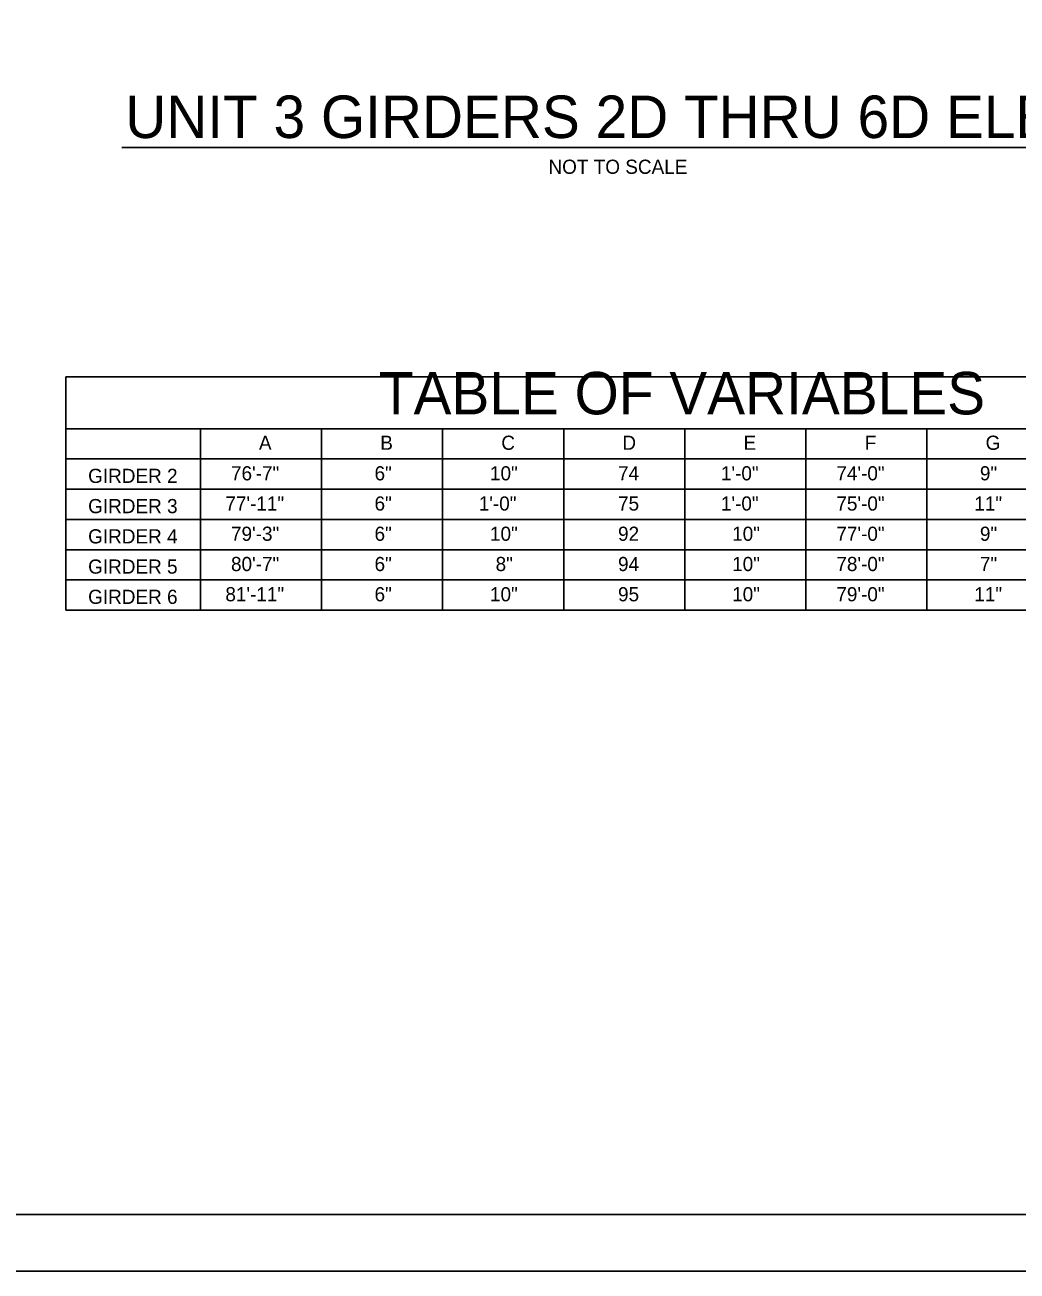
# Model space of a CAD drawing. Extents: x -305 to -161, y -187 to -99.
# Drawn here: x -251.38 to -216.35, y -187.49 to -143.49 of the extents above; entities that cross this region are included whole.
import ezdxf

# ---------------------------------------------------------------- set-up
doc = ezdxf.new("R2010")
doc.units = 0
for name, color, linetype in [('BR_AUTO DIMENSION', 7, 'Continuous'), ('BR_BORDER LINES', 7, 'Continuous'), ('BR_TEXT', 7, 'Continuous'), ('Level 31', 7, 'Continuous')]:
    doc.layers.add(name, color=color, linetype=linetype)

msp = doc.modelspace()

# ---------------------------------------------------------------- linework, layer by layer
at = {"layer": 'BR_AUTO DIMENSION'}
for p, q in [((-249.938, -155.913), (-249.938, -164.154)), ((-249.938, -155.913), (-210.987, -155.913)), ((-249.938, -157.747), (-210.987, -157.747)), ((-245.184, -157.747), (-245.184, -164.154)), ((-240.91, -157.747), (-240.91, -164.154)), ((-236.635, -157.747), (-236.635, -164.154)), ((-232.36, -157.747), (-232.36, -164.154)), ((-228.085, -157.747), (-228.085, -164.154)), ((-223.811, -157.747), (-223.811, -164.154)), ((-219.536, -157.747), (-219.536, -164.154)), ((-249.938, -158.815), (-210.987, -158.815)), ((-249.938, -159.882), (-210.987, -159.882)), ((-249.938, -160.95), (-210.987, -160.95)), ((-249.938, -162.018), (-210.987, -162.018)), ((-249.938, -163.086), (-210.987, -163.086)), ((-249.938, -164.154), (-210.987, -164.154))]:
    msp.add_line(p, q, dxfattribs=at)
at = {"layer": 'BR_BORDER LINES'}
msp.add_line((-297.843, -185.489), (-163.178, -185.489), dxfattribs=at)
at = {"layer": 'BR_TEXT'}
msp.add_line((-247.961, -147.82), (-213.232, -147.82), dxfattribs=at)
at = {"layer": 'Level 31'}
msp.add_lwpolyline([(-305.176, -187.489), (-161.176, -187.489), (-161.176, -99.489), (-305.176, -99.489)], close=True, dxfattribs=at)

# ---------------------------------------------------------------- texts
at = {"layer": 'BR_TEXT'}
for s, height, p in [('UNIT 3 GIRDERS 2D THRU 6D ELEVATION', 1.5, (-247.841, -147.483)), ('NOT TO SCALE', 0.5, (-232.898, -148.747)), ('TABLE OF VARIABLES', 1.5, (-238.887, -157.24))]:
    msp.add_text(s, height=height, dxfattribs=at).set_placement(p)
for s, p in [('A', (-243.12, -158.492)), ('B', (-238.837, -158.492)), ('C', (-234.563, -158.492)), ('D', (-230.29, -158.492)), ('E', (-226.012, -158.492)), ('F', (-221.729, -158.492)), ('G', (-217.464, -158.492)), ('GIRDER 2', (-249.151, -159.661)), ('76\'-7"', (-244.107, -159.57)), ('6"', (-239.039, -159.57)), ('10"', (-234.963, -159.57)), ('74', (-230.442, -159.57)), ('1\'-0"', (-226.81, -159.57)), ('74\'-0"', (-222.734, -159.57)), ('9"', (-217.666, -159.57)), ('77\'-11"', (-244.306, -160.637)), ('6"', (-239.039, -160.637)), ('1\'-0"', (-235.36, -160.637)), ('75', (-230.442, -160.637)), ('1\'-0"', (-226.81, -160.637)), ('75\'-0"', (-222.734, -160.637)), ('11"', (-217.864, -160.637)), ('GIRDER 3', (-249.151, -160.729)), ('GIRDER 4', (-249.151, -161.796)), ('79\'-3"', (-244.107, -161.705)), ('6"', (-239.039, -161.705)), ('10"', (-234.963, -161.705)), ('92', (-230.442, -161.705)), ('10"', (-226.413, -161.705)), ('77\'-0"', (-222.734, -161.705)), ('9"', (-217.666, -161.705)), ('GIRDER 5', (-249.151, -162.864)), ('80\'-7"', (-244.107, -162.773)), ('6"', (-239.039, -162.773)), ('8"', (-234.764, -162.773)), ('94', (-230.442, -162.773)), ('10"', (-226.413, -162.773)), ('78\'-0"', (-222.734, -162.773)), ('7"', (-217.666, -162.773)), ('GIRDER 6', (-249.151, -163.932)), ('81\'-11"', (-244.306, -163.841)), ('6"', (-239.039, -163.841)), ('10"', (-234.963, -163.841)), ('95', (-230.442, -163.841)), ('10"', (-226.413, -163.841)), ('79\'-0"', (-222.734, -163.841)), ('11"', (-217.864, -163.841))]:
    msp.add_text(s, height=0.5, rotation=360, dxfattribs=at).set_placement(p)

doc.saveas('drawing.dxf')
